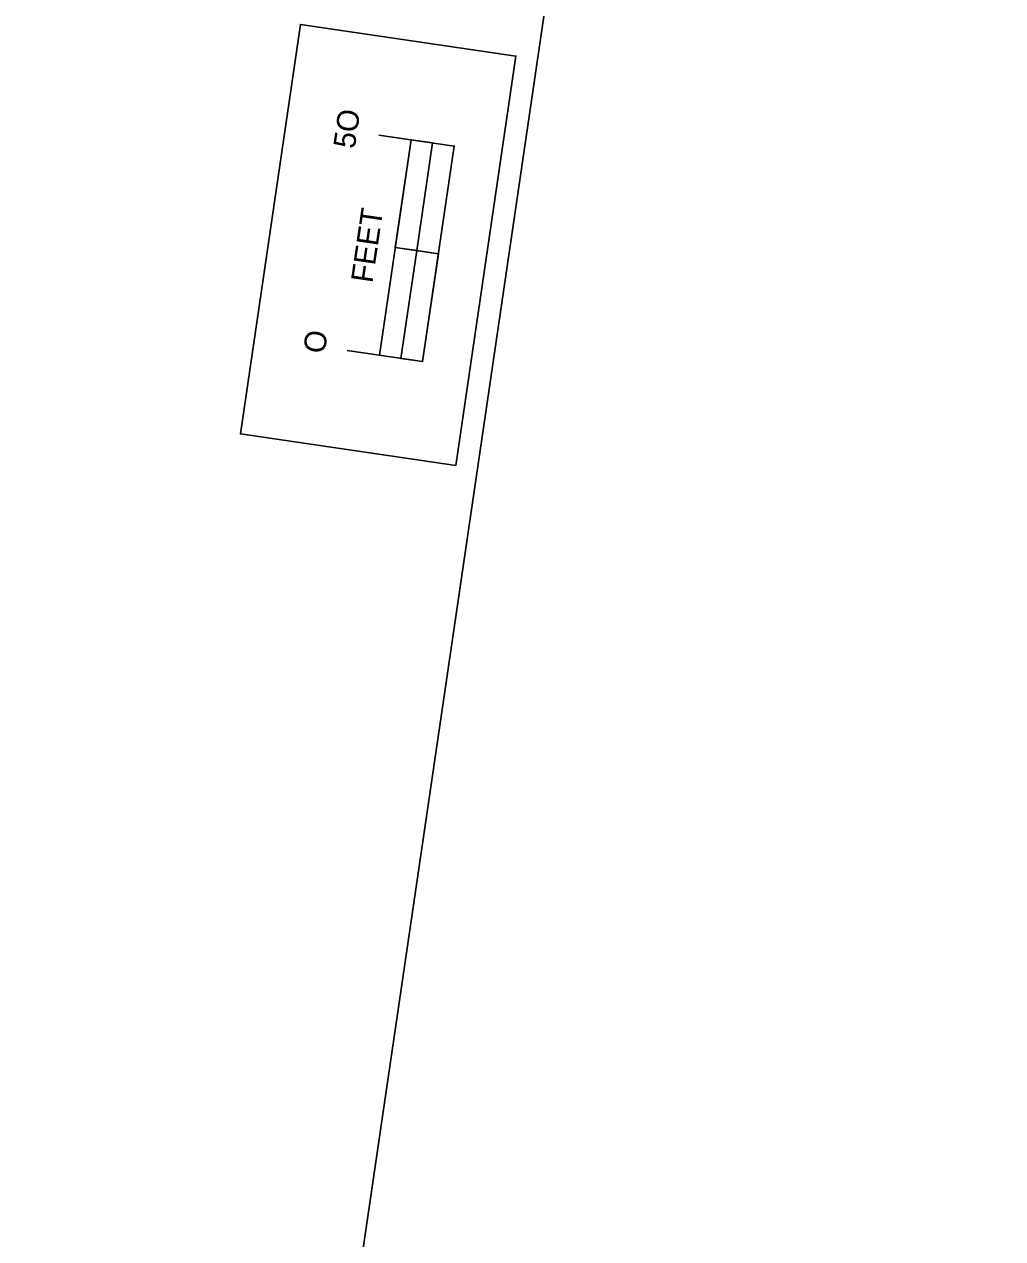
# Model space of a CAD drawing. Extents: x 14104283 to 14120882, y 8635219 to 8671666.
# Drawn here: x 14119276.6 to 14119501.3, y 8669626.2 to 8669905 of the extents above; entities that cross this region are included whole.
import ezdxf

# ---------------------------------------------------------------- set-up
doc = ezdxf.new("R2010")
doc.units = 0
doc.layers.add('dsnNonPlotable', color=7, linetype='Continuous')
doc.layers.add('dsnTextOverlapEven', color=7, linetype='Continuous')

msp = doc.modelspace()

# ---------------------------------------------------------------- linework, layer by layer
at = {"layer": 'dsnNonPlotable'}
msp.add_lwpolyline([(14118774.15, 8669147.84), (14119001.66, 8670698.74), (14119501.31, 8670625.45), (14119273.81, 8669074.54)], close=True, dxfattribs=at)
at = {"layer": 'dsnTextOverlapEven'}
msp.add_line((14119371.73, 8669852.32), (14119361.83, 8669853.77), dxfattribs=at)
msp.add_line((14119371.73, 8669852.32), (14119361.83, 8669853.77), dxfattribs=at)
msp.add_line((14119371.73, 8669852.32), (14119361.83, 8669853.77), dxfattribs=at)
msp.add_line((14119371.73, 8669852.32), (14119361.83, 8669853.77), dxfattribs=at)
for points in [[(14119326.25, 8669810.98), (14119340.04, 8669904.97), (14119389.51, 8669897.72), (14119375.72, 8669803.72)], [(14119375.72, 8669803.72), (14119326.25, 8669810.98), (14119340.04, 8669904.97), (14119389.51, 8669897.72)], [(14119326.25, 8669810.98), (14119340.04, 8669904.97), (14119389.51, 8669897.72), (14119375.72, 8669803.72)], [(14119375.72, 8669803.72), (14119326.25, 8669810.98), (14119340.04, 8669904.97), (14119389.51, 8669897.72)], [(14119366.75, 8669853.05), (14119370.38, 8669877.78), (14119365.46, 8669878.5), (14119361.83, 8669853.77)], [(14119366.75, 8669853.05), (14119370.38, 8669877.78), (14119365.46, 8669878.5), (14119361.83, 8669853.77)], [(14119368.1, 8669827.58), (14119371.73, 8669852.32), (14119366.75, 8669853.05), (14119363.12, 8669828.31)], [(14119368.1, 8669827.58), (14119371.73, 8669852.32), (14119366.75, 8669853.05), (14119363.12, 8669828.31)]]:
    msp.add_lwpolyline(points, close=True, dxfattribs=at)
for points in [[(14119350.79, 8669830.12), (14119368.1, 8669827.58), (14119375.36, 8669877.05), (14119358.04, 8669879.59)], [(14119350.79, 8669830.12), (14119368.1, 8669827.58), (14119375.36, 8669877.05), (14119358.04, 8669879.59)], [(14119358.21, 8669829.03), (14119365.46, 8669878.5)], [(14119358.21, 8669829.03), (14119365.46, 8669878.5)]]:
    msp.add_lwpolyline(points, dxfattribs=at)

# ---------------------------------------------------------------- texts
for s, p in [('5O', (14119352.5, 8669876.29)), ('5O', (14119352.5, 8669876.29)), ('FEET', (14119356.57, 8669845.47)), ('FEET', (14119356.57, 8669845.47)), ('O', (14119345.6, 8669829.23)), ('O', (14119345.6, 8669829.23))]:
    msp.add_text(s, height=5, rotation=81.6547, dxfattribs=at).set_placement(p)

doc.saveas('drawing.dxf')
